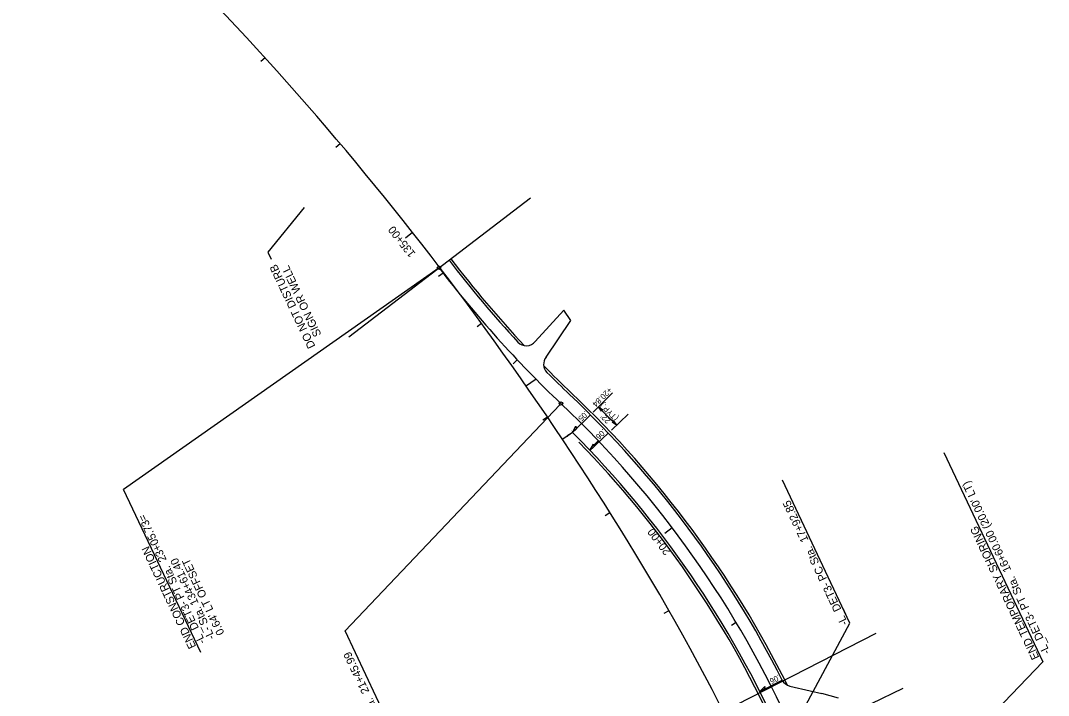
# Model space of a CAD drawing. Extents: x 473658 to 481584, y 489119 to 506230.
# Drawn here: x 477071 to 477969, y 499575 to 500165 of the extents above; entities that cross this region are included whole.
import ezdxf

# ---------------------------------------------------------------- set-up
doc = ezdxf.new("R2010")
doc.units = 0
for name, color, linetype in [('Prop EOT', 7, 'Continuous'), ('Prop Horizontal Alignment', 7, 'Continuous'), ('Prop Horizontal Alignment Station Label', 7, 'Continuous'), ('Prop Horizontal Alignment Tick Label', 7, 'Continuous'), ('Prop Horizontal Alignment Tick Large', 7, 'Continuous'), ('Prop Horizontal Alignment Tick Small', 7, 'Continuous'), ('Prop Paved Shoulder', 7, 'Continuous'), ('Prop Superelevation  Arrow CELL', 7, 'Continuous'), ('Prop Superelevation Label', 7, 'Continuous'), ('Scratch_Level_4', 7, 'Continuous'), ('Scratch_Level_6', 7, 'Continuous'), ('Scratch_Level_9', 7, 'Continuous'), ('Sheet Plan And Profile CELL', 7, 'Continuous'), ('Sheet Profile Grid Major CELL', 7, 'Continuous')]:
    doc.layers.add(name, color=color, linetype=linetype)

msp = doc.modelspace()

# ---------------------------------------------------------------- linework, layer by layer
at = {"layer": 'Prop EOT'}
for p, q in [((477545.59, 499912.08), (477520.68, 499884.7)), ((477551.98, 499903.09), (477545.59, 499912.08)), ((477530.26, 499871.1), (477551.98, 499903.09)), ((477785.86, 499572.68), (477771.43, 499576.81))]:
    msp.add_line(p, q, dxfattribs=at)
msp.add_lwpolyline([(477743.45, 499583.26), (477761.25, 499579.27), (477771.43, 499576.81)], dxfattribs=at)
for centre, radius, start, end in [((478231.65, 500555.71), 989, 217.33789, 222.76392), ((477512.91, 499890.99), 10, 222.76392, 321.04511), ((477538.04, 499864.81), 10, 141.04511, 224.88777), ((478231.65, 500555.71), 989, 224.88777, 226.49452), ((476923.64, 499177.62), 911, 26.80423, 46.49452), ((476923.64, 499177.62), 889, 24.00169, 44.89268), ((477745.64, 499593.02), 10, 206.80968, 257.35581)]:
    msp.add_arc(centre, radius, start, end, dxfattribs=at)
at = {"layer": 'Prop Horizontal Alignment'}
for centre, radius, start, end in [((475172.81, 498218.83), 2850, 31.27221, 48.24762), ((478231.65, 500555.71), 1000, 217.33789, 226.49452), ((476923.64, 499177.62), 900, 24.00169, 46.49452), ((475792.47, 498595.18), 2125, 7.92268, 31.27221)]:
    msp.add_arc(centre, radius, start, end, dxfattribs=at)
at = {"layer": 'Prop Horizontal Alignment Station Label'}
for p, q in [((477436.58, 499949.19), (477160.72, 499755.35)), ((477542.19, 499829.31), (477354.44, 499631.5)), ((477878.12, 499787.67), (477964.72, 499604.42)), ((477795.95, 499638.28), (477736.87, 499763.31)), ((477228.17, 499612.61), (477160.72, 499755.35)), ((477744.45, 499543.1), (477795.95, 499638.28)), ((477415.69, 499501.9), (477354.44, 499631.5)), ((477964.72, 499604.42), (477780.22, 499413.6))]:
    msp.add_line(p, q, dxfattribs=at)
for centre in [(477436.58, 499949.19), (477543.22, 499830.4)]:
    msp.add_circle(centre, 1.5, dxfattribs=at)
at = {"layer": 'Prop Horizontal Alignment Tick Large'}
for p, q in [((477413.44, 499980.1), (477407.15, 499975.15)), ((477640.56, 499721.71), (477634.18, 499716.88))]:
    msp.add_line(p, q, dxfattribs=at)
at = {"layer": 'Prop Horizontal Alignment Tick Small'}
for p, q in [((477284.43, 500132.87), (477280.72, 500129.51)), ((477350.27, 500057.61), (477346.45, 500054.39)), ((477440.07, 499944.64), (477436.11, 499941.59)), ((477473.84, 499900.41), (477469.81, 499897.46)), ((477505.05, 499868.64), (477501.42, 499865.21)), ((477531.42, 499818.65), (477527.28, 499815.85)), ((477575.77, 499797.89), (477572.15, 499794.44)), ((477586.09, 499734.93), (477581.86, 499732.27)), ((477637.62, 499649.24), (477633.28, 499646.76)), ((477696.49, 499638.82), (477692.2, 499636.26))]:
    msp.add_line(p, q, dxfattribs=at)
at = {"layer": 'Prop Paved Shoulder'}
for centre, radius, start, end in [((478231.65, 500555.71), 987, 217.33789, 223.11364), ((478231.65, 500555.71), 987, 224.53804, 226.49452), ((476923.64, 499177.62), 913, 26.43478, 46.49452), ((476923.64, 499177.62), 887, 24.71106, 44.25141)]:
    msp.add_arc(centre, radius, start, end, dxfattribs=at)
at = {"layer": 'Prop Superelevation  Arrow CELL'}
for points in [[(477578.57, 499823.76), (477575.95, 499827.49), (477579.7, 499824.85), (477578.73, 499824.69)], [(477589.21, 499815.27), (477591.84, 499811.53), (477588.08, 499814.17), (477589.05, 499814.33)], [(477553.43, 499805.06), (477556.27, 499810.72), (477556.71, 499808.33)], [(477568.59, 499789.47), (477571.57, 499795.06), (477571.95, 499792.66)], [(477717.12, 499578.51), (477721.58, 499583), (477721.25, 499580.6)]]:
    msp.add_lwpolyline(points, close=True, dxfattribs=at)
at = {"layer": 'Prop Superelevation Label'}
for p, q in [((477571.43, 499822.99), (477588.3, 499839.8)), ((477553.43, 499805.06), (477569.02, 499820.59)), ((477587.35, 499807.27), (477601.96, 499821.13)), ((477568.59, 499789.47), (477584.55, 499804.62)), ((477717.12, 499578.51), (477736.76, 499588.43))]:
    msp.add_line(p, q, dxfattribs=at)
msp.add_arc((479375.7, 501603.96), 2528.83, 224.62695, 225.13728, dxfattribs=at)
at = {"layer": 'Scratch_Level_4'}
msp.add_line((477521.4, 499851.76), (477512.17, 499845.34), dxfattribs=at)
at = {"layer": 'Scratch_Level_6'}
for p, q in [((477553.44, 499805.06), (477543.96, 499798.73)), ((477549.15, 499802.56), (477551.15, 499803.89))]:
    msp.add_line(p, q, dxfattribs=at)
msp.add_lwpolyline([(477549.15, 499802.56), (477549.54, 499803.06), (477549.54, 499802.82)], close=True, dxfattribs=at)
at = {"layer": 'Scratch_Level_9'}
msp.add_line((477357.64, 499888.86), (477516.53, 500010.32), dxfattribs=at)
at = {"layer": 'Sheet Plan And Profile CELL'}
for p, q in [((477551.56, 499493.08), (477818.77, 499629.47)), ((477572.2, 499451.44), (477842.54, 499581.51))]:
    msp.add_line(p, q, dxfattribs=at)
at = {"layer": 'Sheet Profile Grid Major CELL'}
for p, q in [((477318.56, 500002.03), (477286.94, 499962.96)), ((477286.94, 499962.96), (477289.93, 499956.62))]:
    msp.add_line(p, q, dxfattribs=at)

# ---------------------------------------------------------------- texts
at = {"layer": 'Prop Horizontal Alignment Station Label'}
for s, p in [("-L_DET3- PT Sta.  16+60.00 (20.00' LT)", (477971.15, 499612.89)), ('-L_DET3- PC Sta.  17+92.85', (477794.4, 499638.13)), ('-L_DET3- PT Sta.  23+05.73=', (477232.58, 499621.88)), ('END TEMPORARY SHORING', (477961.66, 499608.4)), ('END CONSTRUCTION', (477224.32, 499617.97)), ('-L- Sta. 134+61.40', (477240.84, 499625.78)), ("0.64' LT OFFSET", (477249.1, 499629.68)), ('-L_DET3- PRC Sta.  21+45.99', (477413.15, 499499.51))]:
    msp.add_text(s, height=7, rotation=115.2938, dxfattribs=at).set_placement(p)
at = {"layer": 'Prop Horizontal Alignment Tick Label'}
for s, rotation, p in [('135+00', 128.16945, (477416.44, 499961.71)), ('20+00', 127.19603, (477639.77, 499701.18))]:
    msp.add_text(s, height=7, rotation=rotation, dxfattribs=at).set_placement(p)
at = {"layer": 'Prop Superelevation  Arrow CELL'}
for s, rotation, p in [('+20.84', 224.89291, (477584.96, 499845.13)), ('.05', 224.89291, (477564.35, 499824.51)), ('.06', 223.49162, (477579.89, 499808.58)), ('.06', 206.80423, (477733.43, 499593.56))]:
    msp.add_text(s, height=5, rotation=rotation, dxfattribs=at).set_placement(p)
at = {"layer": 'Prop Superelevation Label'}
for s, p in [('(TYP.)', (477593.81, 499818.18)), ("22'", (477586.93, 499815.81))]:
    msp.add_text(s, height=5, rotation=134.85053, dxfattribs=at).set_placement(p)
at = {"layer": 'Scratch_Level_6'}
for s, rotation, p in [('1672.30', 128.44881, (477553.83, 499805.37)), ('1671.74', 128.44881, (477544.36, 499799.04)), ("11.39'", 213.74667, (477550.04, 499802.19)), ('.049', 213.74667, (477550.49, 499804.3))]:
    msp.add_text(s, height=0.5, rotation=rotation, dxfattribs=at).set_placement(p)
at = {"layer": 'Sheet Profile Grid Major CELL'}
for s, p in [('DO NOT DISTURB ', (477328.6, 499880.55)), ('SIGN OR WELL', (477333.86, 499890.8))]:
    msp.add_text(s, height=7, rotation=115.2938, dxfattribs=at).set_placement(p)

doc.saveas('drawing.dxf')
